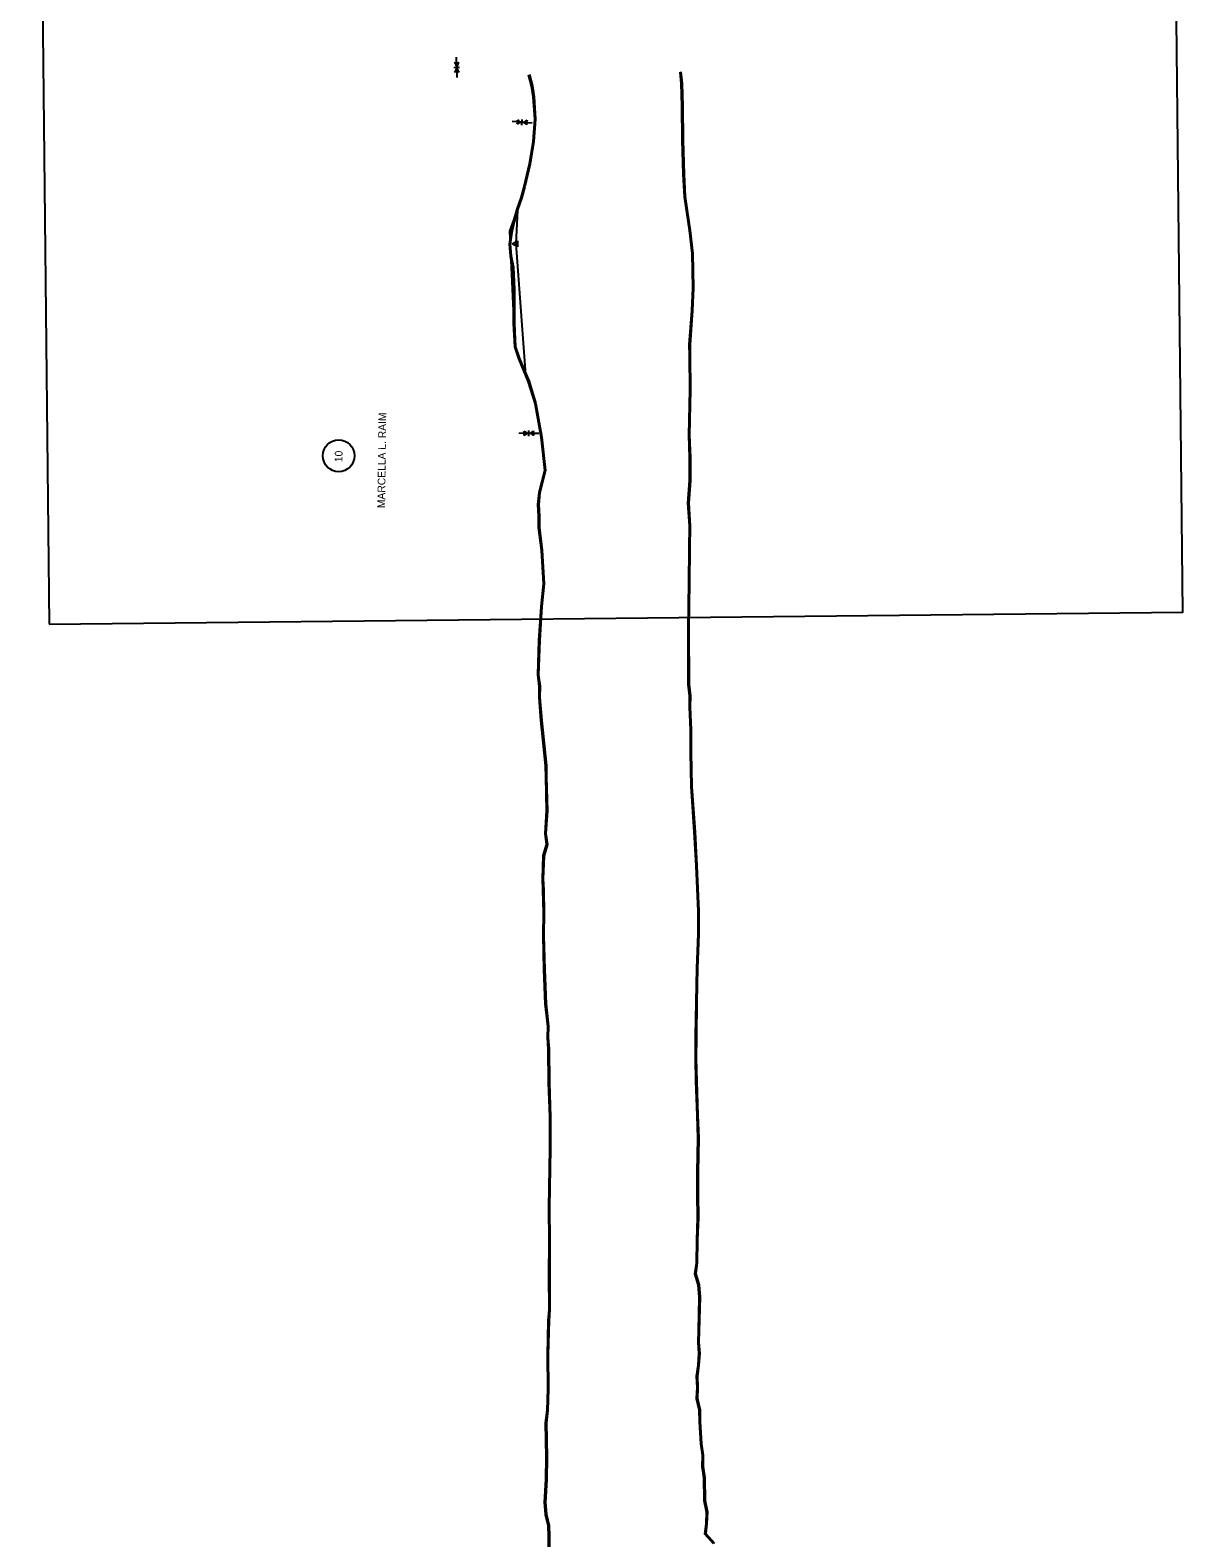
# Model space of a CAD drawing. Extents: x 20504422 to 20508365, y 7965199 to 7983597.
# Drawn here: x 20504422 to 20506455, y 7978830 to 7981489 of the extents above; entities that cross this region are included whole.
import ezdxf

# ---------------------------------------------------------------- set-up
doc = ezdxf.new("R2010")
doc.units = 0
for name, color, linetype in [('SurControl', 7, 'Continuous'), ('SurDikeDam', 7, 'Continuous'), ('SurLotCorner', 7, 'Continuous'), ('SurRipRap', 7, 'Continuous'), ('SurTopOfWater', 7, 'Continuous'), ('SurWetlands', 7, 'Continuous')]:
    doc.layers.add(name, color=color, linetype=linetype)

msp = doc.modelspace()

# ---------------------------------------------------------------- linework, layer by layer
at = {"layer": 'SurControl'}
msp.add_circle((20504966, 7980738.3), 28, dxfattribs=at)
at = {"layer": 'SurDikeDam'}
msp.add_lwpolyline([(20505295.9, 7980881.7), (20505277.2, 7980930.5), (20505268, 7981134.5), (20505281.6, 7981171.6), (20505278.5, 7981112.2)], close=True, dxfattribs=at)
at = {"layer": 'SurLotCorner'}
for p, q in [((20505169.4, 7981423.5), (20505179.5, 7981423.6)), ((20505174.5, 7981423.5), (20505174.2, 7981441.4)), ((20505174.5, 7981423.5), (20505174.8, 7981405.7)), ((20505289.7, 7981326.6), (20505271.9, 7981327.7)), ((20505289.4, 7981321.6), (20505290, 7981331.7)), ((20505289.7, 7981326.6), (20505307.6, 7981325.6)), ((20505272.4, 7981112.3), (20505281.6, 7981117.5)), ((20505281.5, 7981107), (20505272.4, 7981112.3)), ((20505281.6, 7981117.5), (20505281.5, 7981107)), ((20505301.5, 7980778), (20505283.6, 7980777.8)), ((20505301.6, 7980772.9), (20505301.5, 7980783.1)), ((20505301.5, 7980778), (20505319.4, 7980778.2))]:
    msp.add_line(p, q, dxfattribs=at)
for centre, radius, start, end in [((20505174.2, 7981442.7), 11.4, 250.3016, 291.5152), ((20505160, 7981421.8), 14.6, 7.0142, 44.8215), ((20505160, 7981424.9), 14.6, 316.9953, 354.8025), ((20505174.8, 7981404.4), 11.4, 70.3016, 111.5152), ((20505189, 7981422.2), 14.6, 136.9953, 174.8025), ((20505189, 7981425.3), 14.6, 187.0142, 224.8215), ((20505270.6, 7981327.8), 11.4, 335.9522, 17.1659), ((20505290.4, 7981312.1), 14.6, 92.6649, 130.4721), ((20505292.1, 7981341), 14.6, 222.6459, 260.4532), ((20505289, 7981341.2), 14.6, 272.6649, 310.4721), ((20505287.3, 7981312.3), 14.6, 42.6459, 80.4532), ((20505308.9, 7981325.5), 11.4, 155.9522, 197.1659), ((20505302.9, 7980792.5), 14.6, 226.7028, 264.5101), ((20505282.3, 7980777.8), 11.4, 340.0091, 21.2227), ((20505303.2, 7980763.5), 14.6, 96.7218, 134.529), ((20505299.8, 7980792.5), 14.6, 276.7218, 314.529), ((20505300.1, 7980763.5), 14.6, 46.7028, 84.5101), ((20505320.7, 7980778.2), 11.4, 160.0091, 201.2227)]:
    msp.add_arc(centre, radius, start, end, dxfattribs=at)
at = {"layer": 'SurRipRap'}
msp.add_lwpolyline([(20504455.4, 7980441.2), (20506455.3, 7980462.7), (20506421.7, 7983597.5), (20504421.8, 7983576)], close=True, dxfattribs=at)
at = {"layer": 'SurTopOfWater'}
for points in [[(20505300.6, 7981410.1), (20505305.9, 7981390.5), (20505308.8, 7981371.2), (20505311.4, 7981332), (20505308.6, 7981292.8), (20505302, 7981253.3), (20505292.8, 7981213.5), (20505287.4, 7981193.8), (20505280.3, 7981173.8), (20505274.2, 7981153.3), (20505269.7, 7981132.8), (20505266.8, 7981111.7), (20505268.6, 7981090.6), (20505272.3, 7981070.8), (20505274.1, 7981031.4), (20505274, 7980971.4), (20505276.1, 7980930.3), (20505283.4, 7980909.2), (20505300, 7980869.5), (20505311.9, 7980830.3), (20505322.5, 7980771.1), (20505329.1, 7980712.6), (20505319.2, 7980673.3), (20505317.1, 7980652.2), (20505318.1, 7980631.8), (20505318.2, 7980611.6), (20505323.1, 7980571.5), (20505326.6, 7980512.3), (20505322.6, 7980472.6), (20505318.8, 7980412.4), (20505316.8, 7980351.7), (20505319.4, 7980331.6), (20505319.1, 7980311.8), (20505322.2, 7980271.4), (20505330.4, 7980191.7), (20505330.8, 7980172), (20505332.2, 7980112.3), (20505329.6, 7980071.9), (20505332.2, 7980052.7), (20505326.3, 7980033.2), (20505325, 7979992.1), (20505325.7, 7979971.9), (20505326.6, 7979932), (20505326.2, 7979892), (20505327.6, 7979831.9), (20505329.9, 7979771.6), (20505334.5, 7979731.9), (20505333.8, 7979712), (20505335.3, 7979691.9), (20505335.7, 7979632), (20505337.7, 7979572.1), (20505337.8, 7979516.2), (20505336.2, 7979412.2), (20505336.6, 7979352.2), (20505336.4, 7979292.2), (20505336.6, 7979232.4), (20505335.3, 7979212.5), (20505333.7, 7979152.2), (20505334.2, 7979092.2), (20505333, 7979054.7), (20505330.5, 7979032.4), (20505331.8, 7978972.1), (20505331.2, 7978932.3), (20505328.7, 7978892), (20505330.5, 7978871), (20505335.2, 7978851.2), (20505335.8, 7978832), (20505337.7, 7978651.9)], [(20505302.5, 7981410.6), (20505307.8, 7981390.9), (20505310.8, 7981371.4), (20505313.4, 7981332), (20505310.6, 7981292.6), (20505303.9, 7981252.9), (20505294.7, 7981213), (20505289.3, 7981193.2), (20505282.2, 7981173.2), (20505276.1, 7981152.8), (20505271.7, 7981132.4), (20505268.8, 7981111.6), (20505270.6, 7981090.9), (20505274.3, 7981071), (20505276.1, 7981031.5), (20505276, 7980971.5), (20505278.1, 7980930.6), (20505285.2, 7980909.9), (20505301.9, 7980870.2), (20505313.8, 7980830.8), (20505324.5, 7980771.4), (20505331.1, 7980712.5), (20505321.2, 7980672.9), (20505319.1, 7980652.1), (20505320.1, 7980631.9), (20505320.2, 7980611.7), (20505325.1, 7980571.6), (20505328.6, 7980512.2), (20505324.6, 7980472.5), (20505320.8, 7980412.3), (20505318.8, 7980351.8), (20505321.4, 7980331.8), (20505321.1, 7980311.9), (20505324.2, 7980271.6), (20505332.4, 7980191.8), (20505332.8, 7980172), (20505334.2, 7980112.3), (20505331.6, 7980072), (20505334.2, 7980052.6), (20505328.3, 7980032.9), (20505327, 7979992.1), (20505327.7, 7979971.9), (20505328.6, 7979932.1), (20505328.2, 7979892), (20505329.6, 7979831.9), (20505331.9, 7979771.7), (20505336.5, 7979732), (20505335.8, 7979712.1), (20505337.3, 7979692), (20505337.7, 7979632.1), (20505339.7, 7979572.1), (20505339.8, 7979516.2), (20505338.2, 7979412.2), (20505338.6, 7979352.2), (20505338.4, 7979292.2), (20505338.6, 7979232.3), (20505337.3, 7979212.4), (20505335.7, 7979152.2), (20505336.2, 7979092.2), (20505335, 7979054.5), (20505332.5, 7979032.3), (20505333.8, 7978972.1), (20505333.2, 7978932.3), (20505330.7, 7978892), (20505332.5, 7978871.3), (20505337.2, 7978851.5), (20505337.8, 7978832), (20505339.7, 7978651.9)], [(20505567.7, 7981415.2), (20505569.9, 7981395), (20505571.1, 7981354.8), (20505571.6, 7981294.8), (20505573.3, 7981234.9), (20505575.3, 7981195.2), (20505584.4, 7981135.5), (20505589.1, 7981095.2), (20505590.2, 7981034.8), (20505588.2, 7980994.5), (20505583.9, 7980934.7), (20505584.4, 7980914.9), (20505584.7, 7980854.7), (20505583, 7980774.8), (20505584.6, 7980734.9), (20505584.6, 7980694.6), (20505581.6, 7980654.7), (20505584.3, 7980614.9), (20505583.5, 7980574.7), (20505583.2, 7980514.7), (20505582, 7980434.7), (20505582.3, 7980335), (20505584.5, 7980315), (20505584.1, 7980294.8), (20505586, 7980254.9), (20505586.1, 7980214.8), (20505587.3, 7980155), (20505592.7, 7980075.1), (20505595.9, 7980015.1), (20505599.4, 7979935), (20505599.7, 7979914.9), (20505599.4, 7979894.8), (20505597.3, 7979834.7), (20505596, 7979774.8), (20505595.2, 7979714.8), (20505595, 7979674.8), (20505595.7, 7979635), (20505597.8, 7979575), (20505599.2, 7979534.9), (20505598, 7979474.8), (20505598, 7979434.9), (20505598.6, 7979394.8), (20505597.3, 7979354.7), (20505596.5, 7979314.4), (20505594, 7979295.2), (20505599.8, 7979275.8), (20505601.6, 7979254.1), (20505600.1, 7979194.7), (20505599.4, 7979174.9), (20505601, 7979154.9), (20505599.6, 7979134.4), (20505597, 7979114.6), (20505597.9, 7979094.8), (20505596.8, 7979075.3), (20505601.5, 7979055.5), (20505601.8, 7979035), (20505604.2, 7978995.4), (20505607.1, 7978975.2), (20505606.8, 7978955.2), (20505609.8, 7978935.3), (20505610.4, 7978895.5), (20505614.5, 7978875.4), (20505613.7, 7978854.6), (20505611.6, 7978836.6), (20505626.9, 7978819.4)], [(20505569.7, 7981415.4), (20505571.9, 7981395.1), (20505573.1, 7981354.8), (20505573.6, 7981294.8), (20505575.3, 7981235), (20505577.3, 7981195.4), (20505586.4, 7981135.7), (20505591.1, 7981095.3), (20505592.2, 7981034.7), (20505590.2, 7980994.4), (20505585.9, 7980934.6), (20505586.4, 7980914.9), (20505586.7, 7980854.7), (20505585, 7980774.8), (20505586.6, 7980734.9), (20505586.6, 7980694.5), (20505583.6, 7980654.7), (20505586.3, 7980614.9), (20505585.5, 7980574.7), (20505585.2, 7980514.7), (20505584, 7980434.7), (20505584.3, 7980335.1), (20505586.5, 7980315.1), (20505586.1, 7980294.8), (20505588, 7980254.9), (20505588.1, 7980214.8), (20505589.3, 7980155.1), (20505594.7, 7980075.2), (20505597.9, 7980015.2), (20505601.4, 7979935.1), (20505601.7, 7979914.9), (20505601.4, 7979894.7), (20505599.3, 7979834.7), (20505598, 7979774.7), (20505597.2, 7979714.8), (20505597, 7979674.9), (20505597.7, 7979635), (20505599.8, 7979575.1), (20505601.2, 7979534.9), (20505600, 7979474.8), (20505600, 7979434.9), (20505600.6, 7979394.8), (20505599.3, 7979354.7), (20505598.5, 7979314.3), (20505596, 7979295.4), (20505601.8, 7979276.2), (20505603.6, 7979254.2), (20505602.1, 7979194.6), (20505601.4, 7979175), (20505603, 7979154.9), (20505601.6, 7979134.2), (20505599, 7979114.5), (20505599.9, 7979094.8), (20505598.8, 7979075.4), (20505603.5, 7979055.7), (20505603.8, 7979035.1), (20505606.2, 7978995.6), (20505609.1, 7978975.4), (20505608.8, 7978955.4), (20505611.8, 7978935.5), (20505612.4, 7978895.7), (20505616.5, 7978875.6), (20505615.7, 7978854.4), (20505613.7, 7978837.3), (20505628.9, 7978820.2)]]:
    msp.add_lwpolyline(points, dxfattribs=at)
at = {"layer": 'SurWetlands'}
for p, q in [((20505268, 7981134.5), (20505281.6, 7981171.6)), ((20505277.2, 7980930.5), (20505268, 7981134.5)), ((20505295.9, 7980881.7), (20505277.2, 7980930.5))]:
    msp.add_line(p, q, dxfattribs=at)

# ---------------------------------------------------------------- texts
at = {"layer": 'SurControl'}
for s, p in [('MARCELLA L. RAIM', (20505047.9, 7980645.9)), ('10', (20504972.7, 7980727))]:
    msp.add_text(s, height=13.6, rotation=89.2974, dxfattribs=at).set_placement(p)

doc.saveas('drawing.dxf')
